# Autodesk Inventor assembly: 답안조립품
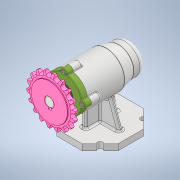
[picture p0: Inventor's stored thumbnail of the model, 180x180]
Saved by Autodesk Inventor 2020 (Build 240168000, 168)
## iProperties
Created: 2021-01
Part Number: 답안조립품
Document SubType Name: Assembly
Designer: pc-05
Author: pc-05
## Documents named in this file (12)
- C:\Users\pc-05\Desktop\710106V1030\답안조립품.iam
- C:\Users\pc-05\Desktop\710106V1030\본체.ipt
- C:\Users\pc-05\Desktop\710106V1030\베어링 51202.ipt
- C:\Users\pc-05\Desktop\710106V1030\어댑터슬리브.ipt
- C:\Users\pc-05\Desktop\710106V1030\베어링 6004.ipt
- C:\Users\pc-05\Desktop\710106V1030\축.ipt
- C:\Users\pc-05\Desktop\710106V1030\커버.ipt
- C:\Users\pc-05\Desktop\710106V1030\키 5 x 5 x 14.ipt
- C:\Users\pc-05\Desktop\710106V1030\스프로킷.ipt
- C:\Users\pc-05\Desktop\710106V1030\멈춤나사 M3.ipt
- C:\Users\pc-05\Desktop\710106V1030\오일 실.ipt
- C:\Users\pc-05\Desktop\710106V1030\볼트 M4.ipt
